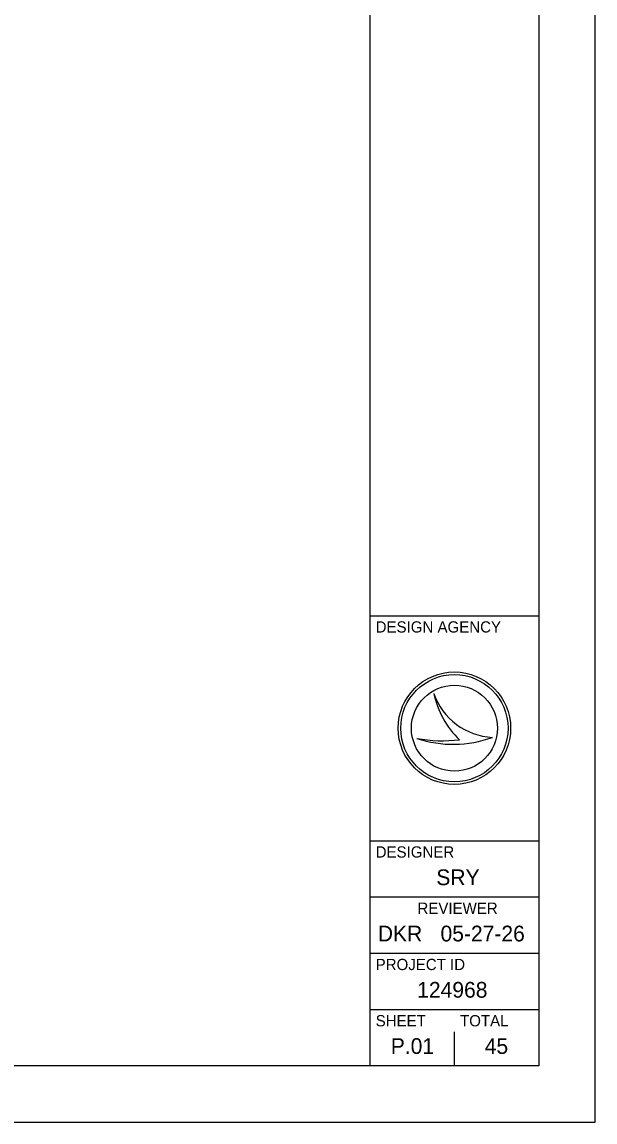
# Model space of a CAD drawing. Extents: x 0 to 34, y 0 to 22.
# Drawn here: x 28.91 to 34, y 0 to 9.78 of the extents above; entities that cross this region are included whole.
import ezdxf

# ---------------------------------------------------------------- set-up
doc = ezdxf.new("R2010")
doc.units = 0
for name, color, linetype in [('SH_Border', 7, 'Continuous'), ('SH_Cut_Line', 7, 'Continuous'), ('SH_Data', 7, 'Continuous')]:
    doc.layers.add(name, color=color, linetype=linetype)

msp = doc.modelspace()

# ---------------------------------------------------------------- linework, layer by layer
at = {"layer": 'SH_Border'}
for p, q in [((32, 0.5), (32, 21.5)), ((32, 4.5), (33.5, 4.5)), ((32, 2.5), (33.5, 2.5)), ((32, 2), (33.5, 2)), ((32, 1.5), (33.5, 1.5)), ((32, 1), (33.5, 1))]:
    msp.add_line(p, q, dxfattribs=at)
msp.add_lwpolyline([(1.5, 21.5), (33.5, 21.5), (33.5, 0.5), (1.5, 0.5)], close=True, dxfattribs=at)
at = {"layer": 'SH_Cut_Line'}
msp.add_lwpolyline([(0, 0), (34, 0), (34, 22), (0, 22)], close=True, dxfattribs=at)
at = {"layer": 'SH_Data'}
for p, q in [((32.5674, 3.8096), (32.5675, 3.8096)), ((32.75, 3.5), (32.75, 3.5)), ((32.4172, 3.4095), (32.4172, 3.4095)), ((33.0873, 3.4185), (33.0873, 3.4185)), ((32.75, 0.5), (32.75, 0.8)), ((32.375, 0.675), (32.375, 0.675))]:
    msp.add_line(p, q, dxfattribs=at)
for radius in [0.5, 0.4768, 0.4768, 0.3822]:
    msp.add_circle((32.75, 3.5), radius, dxfattribs=at)
for centre, radius, start, end in [((33.1159, 3.9976), 0.5798, 198.92567, 198.93195), ((33.3467, 3.9701), 0.7956, 191.63793, 191.64215), ((33.1159, 3.9976), 0.5798, 198.93195, 267.16574), ((33.3467, 3.9701), 0.7956, 191.64215, 226.09467), ((32.7394, 4.37), 1.0131, 251.45764, 290.08324), ((32.648, 4.6543), 1.2661, 259.49639, 259.49952), ((32.7394, 4.37), 1.0131, 251.45274, 251.45764), ((32.648, 4.6543), 1.2661, 259.49952, 276.66723)]:
    msp.add_arc(centre, radius, start, end, dxfattribs=at)

# ---------------------------------------------------------------- texts
for s, height, p in [('DESIGN AGENCY', 0.1, (32.05, 4.35)), ('DESIGNER', 0.1, (32.05, 2.35)), ('SRY', 0.14, (32.589, 2.105)), ('REVIEWER', 0.1, (32.4218, 1.85)), ('DKR', 0.14, (32.0691, 1.605)), ('05-27-26', 0.14, (32.6266, 1.605)), ('PROJECT ID', 0.1, (32.05, 1.35)), ('124968', 0.14, (32.4193, 1.105)), ('SHEET', 0.1, (32.05, 0.85)), ('TOTAL', 0.1, (32.8, 0.85)), ('P.01', 0.14, (32.1844, 0.605)), ('45', 0.14, (33.0197, 0.605))]:
    msp.add_text(s, height=height, dxfattribs=at).set_placement(p)

doc.saveas('drawing.dxf')
